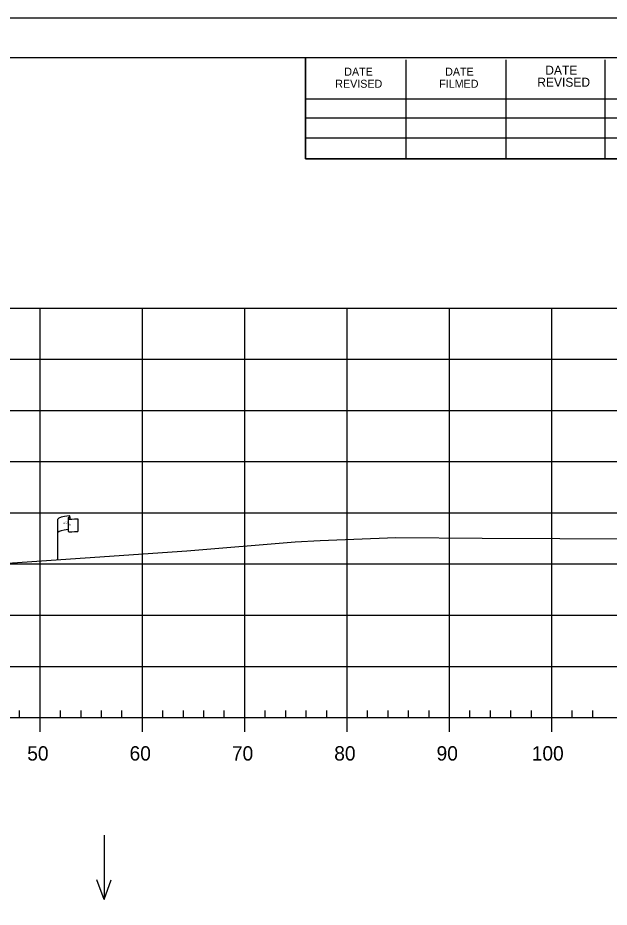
# Model space of a CAD drawing. Extents: x 1370843 to 1371177, y 380307 to 382654.
# Drawn here: x 1371061.5 to 1371119.3, y 381500.6 to 381587.5 of the extents above; entities that cross this region are included whole.
import ezdxf

# ---------------------------------------------------------------- set-up
doc = ezdxf.new("R2010")
doc.units = 0
for name, color, linetype in [('R_Axis', 7, 'Continuous'), ('R_Axis Annot', 7, 'Continuous'), ('R_Border', 7, 'Continuous'), ('R_Exist Surface', 7, 'Continuous'), ('R_Grid', 7, 'Continuous'), ('R_No Plot', 7, 'Continuous'), ('R_ROW', 7, 'Continuous'), ('R_Water Annot', 7, 'Continuous')]:
    doc.layers.add(name, color=color, linetype=linetype)

msp = doc.modelspace()

# ---------------------------------------------------------------- linework, layer by layer
at = {"layer": 'R_Axis'}
for p, q in [((1371061.709, 381519.138), (1371061.709, 381519.838)), ((1371065.709, 381519.138), (1371065.709, 381519.838)), ((1371067.709, 381519.138), (1371067.709, 381519.838)), ((1371069.709, 381519.138), (1371069.709, 381519.838)), ((1371071.709, 381519.138), (1371071.709, 381519.838)), ((1371075.709, 381519.138), (1371075.709, 381519.838)), ((1371077.709, 381519.138), (1371077.709, 381519.838)), ((1371079.709, 381519.138), (1371079.709, 381519.838)), ((1371081.709, 381519.138), (1371081.709, 381519.838)), ((1371085.709, 381519.138), (1371085.709, 381519.838)), ((1371087.709, 381519.138), (1371087.709, 381519.838)), ((1371089.709, 381519.138), (1371089.709, 381519.838)), ((1371091.709, 381519.138), (1371091.709, 381519.838)), ((1371095.709, 381519.138), (1371095.709, 381519.838)), ((1371097.709, 381519.138), (1371097.709, 381519.838)), ((1371099.709, 381519.138), (1371099.709, 381519.838)), ((1371101.709, 381519.138), (1371101.709, 381519.838)), ((1371105.709, 381519.138), (1371105.709, 381519.838)), ((1371107.709, 381519.138), (1371107.709, 381519.838)), ((1371109.709, 381519.138), (1371109.709, 381519.838)), ((1371111.709, 381519.138), (1371111.709, 381519.838)), ((1371115.709, 381519.138), (1371115.709, 381519.838)), ((1371117.709, 381519.138), (1371117.709, 381519.838)), ((1370868.709, 381519.138), (1371158.709, 381519.138)), ((1371063.709, 381517.738), (1371063.709, 381519.138)), ((1371073.709, 381517.738), (1371073.709, 381519.138)), ((1371083.709, 381517.738), (1371083.709, 381519.138)), ((1371093.709, 381517.738), (1371093.709, 381519.138)), ((1371103.709, 381517.738), (1371103.709, 381519.138)), ((1371113.709, 381517.738), (1371113.709, 381519.138))]:
    msp.add_line(p, q, dxfattribs=at)
at = {"layer": 'R_Border'}
for p, q in [((1370855.709, 381583.598), (1371171.889, 381583.598)), ((1371089.629, 381573.718), (1371089.629, 381583.598)), ((1371099.489, 381573.718), (1371099.489, 381583.398)), ((1371109.249, 381573.718), (1371109.249, 381583.398)), ((1371118.929, 381573.718), (1371118.929, 381583.398)), ((1371089.629, 381579.578), (1371128.789, 381579.578)), ((1371089.629, 381577.718), (1371128.789, 381577.718)), ((1371089.629, 381573.718), (1371089.629, 381575.778)), ((1371089.629, 381575.778), (1371128.789, 381575.778)), ((1371171.889, 381573.718), (1371089.629, 381573.718))]:
    msp.add_line(p, q, dxfattribs=at)
at = {"layer": 'R_Exist Surface'}
msp.add_lwpolyline([(1371058.155, 381534.06), (1371078.056, 381535.409), (1371088.634, 381536.316), (1371091.079, 381536.424), (1371098.483, 381536.722), (1371106.915, 381536.672), (1371122.075, 381536.582), (1371125.088, 381536.631), (1371146.201, 381535.967), (1371150.015, 381536.034), (1371158.709, 381535.775)], dxfattribs=at)
at = {"layer": 'R_Grid'}
for p, q in [((1370868.709, 381559.138), (1371158.709, 381559.138)), ((1371063.709, 381519.138), (1371063.709, 381559.138)), ((1371073.709, 381519.138), (1371073.709, 381559.138)), ((1371083.709, 381519.138), (1371083.709, 381559.138)), ((1371093.709, 381519.138), (1371093.709, 381559.138)), ((1371103.709, 381519.138), (1371103.709, 381559.138)), ((1371113.709, 381519.138), (1371113.709, 381559.138)), ((1370868.709, 381554.138), (1371158.709, 381554.138)), ((1370868.709, 381549.138), (1371158.709, 381549.138)), ((1370868.709, 381544.138), (1371158.709, 381544.138)), ((1370868.709, 381539.138), (1371158.709, 381539.138)), ((1370868.709, 381534.138), (1371158.709, 381534.138)), ((1370868.709, 381529.138), (1371158.709, 381529.138)), ((1370868.709, 381524.138), (1371158.709, 381524.138)), ((1370868.709, 381519.138), (1371158.709, 381519.138))]:
    msp.add_line(p, q, dxfattribs=at)
at = {"layer": 'R_No Plot'}
msp.add_line((1370843.308, 381587.493), (1371176.642, 381587.493), dxfattribs=at)
for points in [[(1370843.302, 381587.493), (1371176.642, 381587.493), (1371176.642, 381374.155), (1370843.302, 381374.155)], [(1371089.629, 381583.598), (1371089.629, 381573.718), (1371125.361, 381573.718), (1371125.361, 381570.798), (1371148.561, 381570.798), (1371148.561, 381546.466), (1371171.889, 381546.466), (1371171.889, 381378.138), (1370855.709, 381378.138), (1370855.709, 381583.598)]]:
    msp.add_lwpolyline(points, close=True, dxfattribs=at)
at = {"layer": 'R_ROW'}
for p, q in [((1371066.618, 381538.756), (1371066.618, 381538.516)), ((1371065.455, 381534.555), (1371065.455, 381538.506)), ((1371066.451, 381538.6), (1371066.451, 381538.587)), ((1371066.451, 381538.587), (1371066.451, 381537.36)), ((1371067.386, 381538.563), (1371067.386, 381537.322))]:
    msp.add_line(p, q, dxfattribs=at)
for centre, radius, start, end in [((1371066.54, 381538.756), 0.0783, 263.07118, 93.95638), ((1371066.529, 381538.6), 0.078, 88.6458, 274.28284), ((1371066.529, 381537.36), 0.0783, 180, 273.95638)]:
    msp.add_arc(centre, radius, start, end, dxfattribs=at)
for centre, major_axis, ratio, start_param, end_param in [((1371067.037, 381538.549), (-1.582, -0.043), 0.19887, 5.030368, 6.283185), ((1371067.745, 381538.664), (-1.227, -0.134), 0.052933, 0.159456, 1.268315), ((1371067.032, 381537.231), (-1.582, -0.043), 0.19887, 5.083035, 6.194897), ((1371067.745, 381537.424), (-1.227, -0.134), 0.052933, 0.159456, 1.268315)]:
    msp.add_ellipse(centre, major_axis=major_axis, ratio=ratio, start_param=start_param, end_param=end_param, dxfattribs=at)
at = {"layer": 'R_Water Annot'}
for p, q in [((1371069.956, 381507.645), (1371069.956, 381501.361)), ((1371069.956, 381501.361), (1371069.256, 381503.284)), ((1371069.956, 381501.361), (1371070.656, 381503.284))]:
    msp.add_line(p, q, dxfattribs=at)

# ---------------------------------------------------------------- texts
at = {"layer": 'R_Axis Annot'}
for s, p in [('50', (1371062.448, 381514.938)), ('60', (1371072.448, 381514.938)), ('70', (1371082.448, 381514.938)), ('80', (1371092.448, 381514.938)), ('90', (1371102.448, 381514.938)), ('100', (1371111.748, 381514.938))]:
    msp.add_text(s, height=1.4, dxfattribs=at).set_placement(p)
at = {"layer": 'R_Border'}
for s, height, p in [('DATE', 0.7819, (1371093.429, 381581.838)), ('DATE', 0.7819, (1371103.289, 381581.838)), ('DATE', 0.8792, (1371113.069, 381581.938)), ('REVISED', 0.7819, (1371092.549, 381580.658)), ('FILMED', 0.7819, (1371102.709, 381580.658)), ('REVISED', 0.8792, (1371112.289, 381580.758))]:
    msp.add_text(s, height=height, rotation=360, dxfattribs=at).set_placement(p)
at = {"layer": 'R_ROW'}
for s, height, rotation, p in [('R ', 0.2, 9.98841, (1371065.975, 381538.007)), (' O', 0.2, 9.98841, (1371066.12, 381538.052)), ('W', 0.2, 351.17882, (1371066.45, 381537.883)), ('DWB 11-9-07', 0.001, 90, (1371066.618, 381538.516)), ('DWB 11-9-07', 0.001, 5.07169, (1371067.376, 381537.322)), ('DWB 11-9-07', 0.001, 90, (1371065.455, 381534.555))]:
    msp.add_text(s, height=height, rotation=rotation, dxfattribs=at).set_placement(p)

doc.saveas('drawing.dxf')
